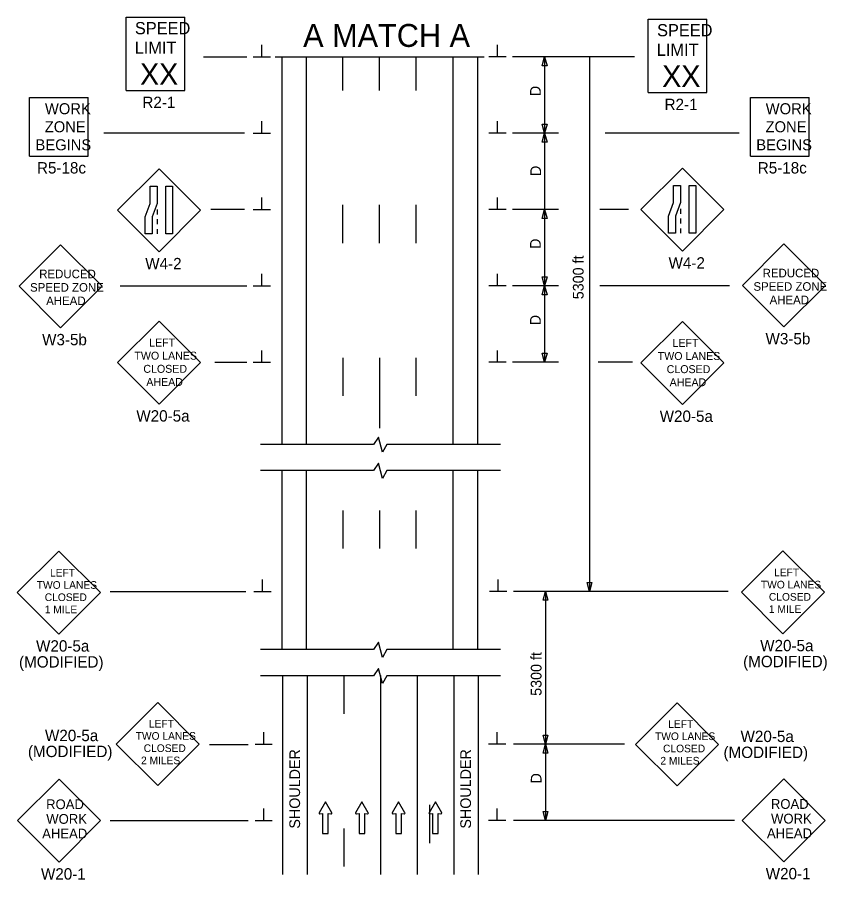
# Model space of a CAD drawing. Extents: x 16486 to 19506, y 5576 to 7023.
# Drawn here: x 17842 to 18372, y 6358 to 6923 of the extents above; entities that cross this region are included whole.
import ezdxf

# ---------------------------------------------------------------- set-up
doc = ezdxf.new("R2010")
doc.units = 0
for name, color, linetype in [('ALI_LEGAL_EX', 7, 'Continuous'), ('MT_SCRATCH_LEVEL_E', 7, 'Continuous'), ('PAVT_EDGE_EX', 7, 'Continuous'), ('TRAFFIC_SIGNS_PR', 7, 'Continuous'), ('TYPICAL_TEXT_DIMEN_PR', 7, 'Continuous')]:
    doc.layers.add(name, color=color, linetype=linetype)

msp = doc.modelspace()

# ---------------------------------------------------------------- linework, layer by layer
at = {"layer": 'ALI_LEGAL_EX'}
for p, q in [((18080.13, 6492.04), (18080.13, 6361.96)), ((18104.13, 6492.04), (18104.13, 6361.96))]:
    msp.add_line(p, q, dxfattribs=at)
for points in [[(18055.61, 6875.22), (18055.61, 6897.24)], [(18079.61, 6875.22), (18079.61, 6897.24)], [(18103.61, 6875.22), (18103.61, 6897.24)], [(18055.61, 6775.22), (18055.61, 6800.22)], [(18079.61, 6775.22), (18079.61, 6800.22)], [(18103.61, 6775.22), (18103.61, 6800.22)], [(18055.61, 6700.22), (18055.61, 6675.22)], [(18079.61, 6700.22), (18079.61, 6675.22)], [(18103.61, 6675.22), (18103.61, 6700.22)], [(18079.61, 6679.08), (18079.61, 6654.08)], [(18055.61, 6600.22), (18055.61, 6575.22)], [(18079.61, 6600.22), (18079.61, 6575.22)], [(18103.61, 6575.22), (18103.61, 6600.22)], [(18056.13, 6492.04), (18056.13, 6467.04)], [(18080.13, 6492.04), (18080.13, 6467.04)], [(18104.13, 6492.04), (18104.13, 6467.04)], [(18112.27, 6407.39), (18112.27, 6382.39)], [(18056.13, 6392.04), (18056.13, 6367.04)], [(18080.13, 6392.04), (18080.13, 6367.04)], [(18104.13, 6392.04), (18104.13, 6367.04)]]:
    msp.add_lwpolyline(points, dxfattribs=at)
at = {"layer": 'MT_SCRATCH_LEVEL_E'}
for p, q in [((18044.13, 6409.47), (18040.02, 6402.23)), ((18048.27, 6402.23), (18044.13, 6409.47)), ((18068.03, 6409.47), (18063.92, 6402.23)), ((18072.18, 6402.23), (18068.03, 6409.47)), ((18092.03, 6409.47), (18087.92, 6402.23)), ((18096.18, 6402.23), (18092.03, 6409.47)), ((18116.08, 6409.47), (18111.97, 6402.23)), ((18120.23, 6402.23), (18116.08, 6409.47)), ((18040.5, 6401.54), (18042.28, 6401.86)), ((18042.28, 6401.86), (18042.28, 6388.6)), ((18046.02, 6388.6), (18046.02, 6401.86)), ((18046.02, 6401.86), (18047.79, 6401.54)), ((18064.4, 6401.54), (18066.18, 6401.86)), ((18066.18, 6401.86), (18066.18, 6388.6)), ((18069.92, 6388.6), (18069.92, 6401.86)), ((18069.92, 6401.86), (18071.7, 6401.54)), ((18088.4, 6401.54), (18090.18, 6401.86)), ((18090.18, 6401.86), (18090.18, 6388.6)), ((18093.92, 6388.6), (18093.92, 6401.86)), ((18093.92, 6401.86), (18095.7, 6401.54)), ((18112.46, 6401.54), (18114.23, 6401.86)), ((18114.23, 6401.86), (18114.23, 6388.6)), ((18117.97, 6388.6), (18117.97, 6401.86)), ((18117.97, 6401.86), (18119.75, 6401.54)), ((18042.28, 6388.6), (18046.02, 6388.6)), ((18066.18, 6388.6), (18069.92, 6388.6)), ((18090.18, 6388.6), (18093.92, 6388.6)), ((18114.23, 6388.6), (18117.97, 6388.6))]:
    msp.add_line(p, q, dxfattribs=at)
for centre, start, end in [((18040.42, 6402), 150.4248, 279.9638), ((18047.86, 6402), 260.0362, 29.7731), ((18064.33, 6402), 150.4248, 279.9638), ((18071.77, 6402), 260.0362, 29.7731), ((18088.33, 6402), 150.4248, 279.9638), ((18095.77, 6402), 260.0362, 29.7731), ((18112.38, 6402), 150.4248, 279.9638), ((18119.82, 6402), 260.0362, 29.7731)]:
    msp.add_arc(centre, 0.463, start, end, dxfattribs=at)
at = {"layer": 'PAVT_EDGE_EX'}
for p, q in [((18015.61, 6897.24), (18015.61, 6643.43)), ((18031.61, 6897.24), (18031.61, 6643.43)), ((18127.61, 6897.24), (18127.61, 6643.43)), ((18143.61, 6897.24), (18143.61, 6643.43)), ((18015.61, 6626.3), (18015.61, 6509.16)), ((18031.61, 6626.3), (18031.61, 6509.16)), ((18127.61, 6626.3), (18127.61, 6509.16)), ((18143.61, 6626.3), (18143.61, 6509.16)), ((18016.13, 6492.02), (18016.13, 6361.96)), ((18032.13, 6492.02), (18032.13, 6361.96)), ((18128.13, 6492.02), (18128.13, 6361.96)), ((18144.13, 6492.02), (18144.13, 6361.96))]:
    msp.add_line(p, q, dxfattribs=at)
at = {"layer": 'TRAFFIC_SIGNS_PR'}
for p, q in [((17913.69, 6923.11), (17952.09, 6923.11)), ((17913.69, 6875.11), (17913.69, 6923.11)), ((17952.09, 6875.11), (17952.09, 6923.11)), ((18255.43, 6921.78), (18293.83, 6921.78)), ((18255.43, 6873.78), (18255.43, 6921.78)), ((18293.83, 6873.78), (18293.83, 6921.78)), ((17913.69, 6875.11), (17952.09, 6875.11)), ((18255.43, 6873.78), (18293.83, 6873.78)), ((17850.57, 6832.25), (17850.57, 6870.65)), ((17850.57, 6870.65), (17888.97, 6870.65)), ((17888.97, 6832.25), (17888.97, 6870.65)), ((18322.3, 6832.25), (18322.3, 6870.65)), ((18322.3, 6870.65), (18360.7, 6870.65)), ((18360.7, 6832.25), (18360.7, 6870.65)), ((17850.57, 6832.25), (17888.97, 6832.25)), ((18322.3, 6832.25), (18360.7, 6832.25)), ((17935.27, 6823.87), (17908.12, 6796.71)), ((17962.42, 6796.71), (17935.27, 6823.87)), ((18277.76, 6824.32), (18250.61, 6797.17)), ((18304.92, 6797.17), (18277.76, 6824.32)), ((17908.12, 6796.71), (17935.27, 6769.56)), ((17934.02, 6797.21), (17934.02, 6794.01)), ((17935.27, 6769.56), (17962.42, 6796.71)), ((18250.61, 6797.17), (18277.76, 6770.01)), ((18276.52, 6797.66), (18276.52, 6794.46)), ((18277.76, 6770.01), (18304.92, 6797.17)), ((17934.02, 6790.81), (17934.02, 6787.61)), ((18276.52, 6791.26), (18276.52, 6788.06)), ((17934.02, 6784.41), (17934.02, 6781.21)), ((18276.52, 6784.86), (18276.52, 6781.66)), ((17870.78, 6774.1), (17843.63, 6746.95)), ((17897.93, 6746.95), (17870.78, 6774.1)), ((18344.23, 6774.69), (18317.08, 6747.54)), ((18371.38, 6747.54), (18344.23, 6774.69)), ((17843.63, 6746.95), (17870.78, 6719.8)), ((17870.78, 6719.8), (17897.93, 6746.95)), ((18317.08, 6747.54), (18344.23, 6720.38)), ((18344.23, 6720.38), (18371.38, 6747.54)), ((17935.27, 6724.15), (17908.12, 6696.99)), ((17962.42, 6696.99), (17935.27, 6724.15)), ((18277.76, 6723.94), (18250.61, 6696.79)), ((18304.92, 6696.79), (18277.76, 6723.94)), ((17908.12, 6696.99), (17935.27, 6669.84)), ((17935.27, 6669.84), (17962.42, 6696.99)), ((18250.61, 6696.79), (18277.76, 6669.63)), ((18277.76, 6669.63), (18304.92, 6696.79)), ((17869.65, 6573.61), (17842.46, 6546.42)), ((17896.84, 6546.42), (17869.65, 6573.61)), ((18343.56, 6573.85), (18316.38, 6546.66)), ((18370.75, 6546.66), (18343.56, 6573.85)), ((17842.46, 6546.42), (17869.65, 6519.24)), ((17869.65, 6519.24), (17896.84, 6546.42)), ((18316.38, 6546.66), (18343.56, 6519.48)), ((18343.56, 6519.48), (18370.75, 6546.66)), ((17934.4, 6474.47), (17907.21, 6447.28)), ((17961.59, 6447.28), (17934.4, 6474.47)), ((18274.27, 6474.27), (18247.09, 6447.08)), ((18301.46, 6447.08), (18274.27, 6474.27)), ((17907.21, 6447.28), (17934.4, 6420.1)), ((17934.4, 6420.1), (17961.59, 6447.28)), ((18247.09, 6447.08), (18274.27, 6419.9)), ((18274.27, 6419.9), (18301.46, 6447.08)), ((17869.81, 6424.27), (17842.65, 6397.12)), ((17896.96, 6397.12), (17869.81, 6424.27)), ((18344.14, 6424.44), (18316.98, 6397.29)), ((18371.29, 6397.29), (18344.14, 6424.44)), ((17842.65, 6397.12), (17869.81, 6369.97)), ((17869.81, 6369.97), (17896.96, 6397.12)), ((18316.98, 6397.29), (18344.14, 6370.14)), ((18344.14, 6370.14), (18371.29, 6397.29))]:
    msp.add_line(p, q, dxfattribs=at)
for points in [[(17934.02, 6812.45), (17934.02, 6801.27), (17930.68, 6792.39), (17930.68, 6781.21), (17926.19, 6781.21), (17926.19, 6792.39), (17929.53, 6801.27), (17929.53, 6812.45)], [(17944.16, 6812.45), (17944.16, 6781.21), (17939.67, 6781.21), (17939.67, 6812.45)], [(18276.52, 6812.9), (18276.52, 6801.72), (18273.17, 6792.84), (18273.17, 6781.66), (18268.68, 6781.66), (18268.68, 6792.84), (18272.02, 6801.72), (18272.02, 6812.9)], [(18286.65, 6812.9), (18286.65, 6781.66), (18282.16, 6781.66), (18282.16, 6812.9)]]:
    msp.add_lwpolyline(points, close=True, dxfattribs=at)
at = {"layer": 'TYPICAL_TEXT_DIMEN_PR'}
for p, q in [((18002.48, 6897.24), (18002.48, 6905.02)), ((18156.73, 6897.24), (18156.73, 6905.02)), ((17964.35, 6897.24), (17992.61, 6897.24)), ((17996.86, 6897.24), (18008.11, 6897.24)), ((18011.28, 6897.24), (18147.93, 6897.24)), ((18162.36, 6897.24), (18151.11, 6897.24)), ((18246.37, 6897.24), (18166.61, 6897.24)), ((18186.04, 6891.37), (18187.61, 6897.24)), ((18187.61, 6897.24), (18187.61, 6847.24)), ((18187.61, 6897.24), (18189.18, 6891.37)), ((18216.99, 6897.24), (18216.99, 6547.24)), ((18187.61, 6891.37), (18186.04, 6891.37)), ((18189.18, 6891.37), (18187.61, 6891.37)), ((18002.48, 6847.24), (18002.48, 6855.02)), ((18156.73, 6847.24), (18156.73, 6855.02)), ((18187.61, 6847.24), (18186.04, 6853.1)), ((18186.04, 6853.1), (18187.61, 6853.1)), ((18187.61, 6853.1), (18189.18, 6853.1)), ((18189.18, 6853.1), (18187.61, 6847.24)), ((17991.11, 6847.24), (17899.04, 6847.24)), ((17996.86, 6847.24), (18008.11, 6847.24)), ((18162.36, 6847.24), (18151.11, 6847.24)), ((18196.69, 6847.24), (18166.61, 6847.24)), ((18186.04, 6841.37), (18187.61, 6847.24)), ((18187.61, 6847.24), (18189.18, 6841.37)), ((18187.61, 6847.24), (18187.61, 6787.24)), ((18314.83, 6847.24), (18227.14, 6847.24)), ((18187.61, 6841.37), (18186.04, 6841.37)), ((18189.18, 6841.37), (18187.61, 6841.37)), ((18002.48, 6797.24), (18002.48, 6805.02)), ((18156.73, 6797.24), (18156.73, 6805.02)), ((17991.11, 6797.24), (17969.12, 6797.24)), ((17996.86, 6797.24), (18008.11, 6797.24)), ((18162.36, 6797.24), (18151.11, 6797.24)), ((18196.69, 6797.24), (18166.61, 6797.24)), ((18186.04, 6791.37), (18187.61, 6797.24)), ((18187.61, 6797.24), (18187.61, 6747.24)), ((18187.61, 6797.24), (18189.18, 6791.37)), ((18242.53, 6797.24), (18223.75, 6797.24)), ((18187.61, 6791.37), (18186.04, 6791.37)), ((18189.18, 6791.37), (18187.61, 6791.37)), ((18002.48, 6747.24), (18002.48, 6755.02)), ((18156.73, 6747.24), (18156.73, 6755.02)), ((18187.61, 6747.24), (18186.04, 6753.1)), ((18186.04, 6753.1), (18187.61, 6753.1)), ((18187.61, 6753.1), (18189.18, 6753.1)), ((18189.18, 6753.1), (18187.61, 6747.24)), ((17909.88, 6747.24), (17992.61, 6747.24)), ((17996.86, 6747.24), (18008.11, 6747.24)), ((18162.36, 6747.24), (18151.11, 6747.24)), ((18196.69, 6747.24), (18166.61, 6747.24)), ((18186.04, 6741.37), (18187.61, 6747.24)), ((18187.61, 6747.24), (18187.61, 6697.24)), ((18187.61, 6747.24), (18189.18, 6741.37)), ((18308.67, 6747.24), (18223.75, 6747.24)), ((18187.61, 6741.37), (18186.04, 6741.37)), ((18189.18, 6741.37), (18187.61, 6741.37)), ((18002.48, 6697.24), (18002.48, 6705.02)), ((18156.73, 6697.24), (18156.73, 6705.02)), ((18187.61, 6697.24), (18186.04, 6703.1)), ((18186.04, 6703.1), (18187.61, 6703.1)), ((18187.61, 6703.1), (18189.18, 6703.1)), ((18189.18, 6703.1), (18187.61, 6697.24)), ((17971.87, 6697.24), (17992.61, 6697.24)), ((17996.86, 6697.24), (18008.11, 6697.24)), ((18162.36, 6697.24), (18151.11, 6697.24)), ((18196.69, 6697.24), (18166.61, 6697.24)), ((18245.16, 6697.24), (18222.62, 6697.24)), ((18078.8, 6648.23), (18075.54, 6643.43)), ((18081.54, 6638.29), (18078.8, 6648.23)), ((18075.54, 6643.43), (18001.63, 6643.43)), ((18084.28, 6643.43), (18081.54, 6638.29)), ((18158.63, 6643.43), (18084.28, 6643.43)), ((18078.8, 6631.1), (18075.54, 6626.3)), ((18081.54, 6621.16), (18078.8, 6631.1)), ((18075.54, 6626.3), (18001.63, 6626.3)), ((18084.28, 6626.3), (18081.54, 6621.16)), ((18158.63, 6626.3), (18084.28, 6626.3)), ((18003, 6547.24), (18003, 6555.02)), ((18157.25, 6547.24), (18157.25, 6555.02)), ((18216.99, 6547.24), (18215.42, 6553.1)), ((18215.42, 6553.1), (18216.99, 6553.1)), ((18216.99, 6553.1), (18218.56, 6553.1)), ((18218.56, 6553.1), (18216.99, 6547.24)), ((17903.37, 6547.24), (17992.08, 6547.24)), ((17997.38, 6547.24), (18008.63, 6547.24)), ((18162.88, 6547.24), (18151.63, 6547.24)), ((18307.73, 6547.24), (18167.13, 6547.24)), ((18186.56, 6541.37), (18188.13, 6547.24)), ((18188.13, 6547.24), (18188.13, 6447.24)), ((18188.13, 6547.24), (18189.7, 6541.37)), ((18188.13, 6541.37), (18186.56, 6541.37)), ((18189.7, 6541.37), (18188.13, 6541.37)), ((18078.8, 6513.96), (18075.54, 6509.16)), ((18081.54, 6504.02), (18078.8, 6513.96)), ((18075.54, 6509.16), (18001.63, 6509.16)), ((18084.28, 6509.16), (18081.54, 6504.02)), ((18158.63, 6509.16), (18084.28, 6509.16)), ((18078.8, 6496.82), (18075.54, 6492.02)), ((18081.54, 6486.88), (18078.8, 6496.82)), ((18075.54, 6492.02), (18001.63, 6492.02)), ((18084.28, 6492.02), (18081.54, 6486.88)), ((18158.63, 6492.02), (18084.28, 6492.02)), ((18003.75, 6447.24), (18003.75, 6455.02)), ((18156.5, 6447.24), (18156.5, 6455.02)), ((18188.13, 6447.24), (18186.56, 6453.1)), ((18186.56, 6453.1), (18188.13, 6453.1)), ((18188.13, 6453.1), (18189.7, 6453.1)), ((18189.7, 6453.1), (18188.13, 6447.24)), ((17968.18, 6447.08), (17993.62, 6447.08)), ((17998.13, 6447.24), (18009.38, 6447.24)), ((18162.13, 6447.24), (18150.88, 6447.24)), ((18239.92, 6447.24), (18167.13, 6447.24)), ((18186.56, 6441.37), (18188.13, 6447.24)), ((18188.13, 6447.24), (18188.13, 6397.24)), ((18188.13, 6447.24), (18189.7, 6441.37)), ((18188.13, 6441.37), (18186.56, 6441.37)), ((18189.7, 6441.37), (18188.13, 6441.37)), ((18003.75, 6397.24), (18003.75, 6405.02)), ((18156.5, 6397.24), (18156.5, 6405.02)), ((18188.13, 6397.24), (18186.56, 6403.1)), ((18186.56, 6403.1), (18188.13, 6403.1)), ((18188.13, 6403.1), (18189.7, 6403.1)), ((18189.7, 6403.1), (18188.13, 6397.24)), ((17903.37, 6397.24), (17993.62, 6397.24)), ((17998.13, 6397.24), (18009.38, 6397.24)), ((18162.13, 6397.24), (18150.88, 6397.24)), ((18311.95, 6397.24), (18167.13, 6397.24))]:
    msp.add_line(p, q, dxfattribs=at)

# ---------------------------------------------------------------- texts
at = {"layer": 'TRAFFIC_SIGNS_PR'}
for s, height, p in [('SPEED', 8, (17919.46, 6911.98)), ('SPEED', 8, (18261.2, 6910.64)), ('LIMIT', 8, (17919.3, 6899.18)), ('LIMIT', 8, (18261.03, 6897.84)), ('XX', 14.031, (17922.8, 6878.87)), ('XX', 14.031, (18264.54, 6877.54)), ('WORK', 7.217, (17860.57, 6859.61)), ('R2-1', 7.44, (17924.37, 6863.67)), ('R2-1', 7.44, (18266.11, 6862.34)), ('WORK', 7.217, (18332.3, 6859.61)), ('ZONE', 7.217, (17860.45, 6847.8)), ('ZONE', 7.217, (18332.18, 6847.8)), ('BEGINS', 7.217, (17854.38, 6835.99)), ('BEGINS', 7.217, (18326.11, 6835.99)), ('R5-18c', 7.44, (17855.38, 6820.81)), ('R5-18c', 7.44, (18327.11, 6820.81)), ('W4-2', 7.44, (17926.23, 6758.12)), ('W4-2', 7.44, (18268.72, 6758.57)), ('REDUCED', 5.6, (17856.84, 6752.26)), ('REDUCED', 5.6, (18330.29, 6752.84)), ('SPEED ZONE', 5.6, (17850.83, 6743.46)), ('SPEED ZONE', 5.6, (18324.28, 6744.04)), ('AHEAD', 5.6, (17861.39, 6734.66)), ('AHEAD', 5.6, (18334.84, 6735.24)), ('W3-5b', 7.44, (17858.73, 6708.36)), ('W3-5b', 7.44, (18332.18, 6708.94)), ('LEFT', 5.2, (17928.81, 6707.53)), ('LEFT', 5.2, (18271.3, 6707.32)), ('TWO LANES', 5.2, (17919.14, 6698.93)), ('TWO LANES', 5.2, (18261.63, 6698.72)), ('CLOSED', 5.2, (17924.99, 6690.33)), ('CLOSED', 5.2, (18267.48, 6690.12)), ('AHEAD', 5.2, (17926.93, 6681.73)), ('AHEAD', 5.2, (18269.42, 6681.52)), ('W20-5a', 7.44, (17920.41, 6658.4)), ('W20-5a', 7.44, (18262.91, 6658.19)), ('LEFT', 5.006, (17863.89, 6556.92)), ('LEFT', 5.006, (18337.81, 6557.15)), ('TWO LANES', 5.006, (17855.24, 6548.91)), ('TWO LANES', 5.006, (18329.15, 6549.15)), ('CLOSED', 5.006, (17860.47, 6540.9)), ('CLOSED', 5.006, (18334.39, 6541.14)), ('1 MILE', 5.006, (17860.47, 6532.89)), ('1 MILE', 5.006, (18334.38, 6533.13)), ('W20-5a', 7.449, (17854.77, 6507.78)), ('W20-5a', 7.449, (18328.68, 6508.02)), ('(MODIFIED)', 7.449, (18317.52, 6497.57)), ('(MODIFIED)', 7.449, (17843.61, 6497.33)), ('LEFT', 5.006, (17928.64, 6458.08)), ('LEFT', 5.006, (18268.52, 6457.88)), ('W20-5a', 7.449, (17860.6, 6449.17)), ('TWO LANES', 5.006, (17919.99, 6450.07)), ('TWO LANES', 5.006, (18259.86, 6449.87)), ('W20-5a', 7.449, (18315.83, 6448.58)), ('(MODIFIED)', 7.449, (17849.44, 6438.72)), ('CLOSED', 5.006, (17925.22, 6442.06)), ('CLOSED', 5.006, (18265.1, 6441.86)), ('(MODIFIED)', 7.449, (18304.67, 6438.13)), ('2 MILES', 5.006, (17923.47, 6434.05)), ('2 MILES', 5.006, (18263.34, 6433.85)), ('ROAD', 6.4, (17861.35, 6404.65)), ('ROAD', 6.4, (18335.68, 6404.83)), ('WORK', 6.4, (17861.46, 6395.05)), ('WORK', 6.4, (18335.79, 6395.23)), ('AHEAD', 6.4, (17858.77, 6385.45)), ('AHEAD', 6.4, (18333.1, 6385.63)), ('W20-1', 7.44, (17857.98, 6358.53)), ('W20-1', 7.44, (18332.31, 6358.7))]:
    msp.add_text(s, height=height, dxfattribs=at).set_placement(p)
at = {"layer": 'TYPICAL_TEXT_DIMEN_PR'}
msp.add_text('A MATCH A', height=15, dxfattribs=at).set_placement((18029.57, 6903.7))
for s, p in [('D', (18185.05, 6871.45)), ('D', (18185.26, 6819.17)), ('D', (18185.05, 6771.45)), ('5300 ft', (18213.1, 6738.48)), ('D', (18185.05, 6721.45)), ('5300 ft', (18185.57, 6478.84)), ('SHOULDER', (18027.55, 6391.89)), ('SHOULDER', (18139.41, 6391.89)), ('D', (18185.57, 6421.46))]:
    msp.add_text(s, height=7, rotation=90, dxfattribs=at).set_placement(p)

doc.saveas('drawing.dxf')
